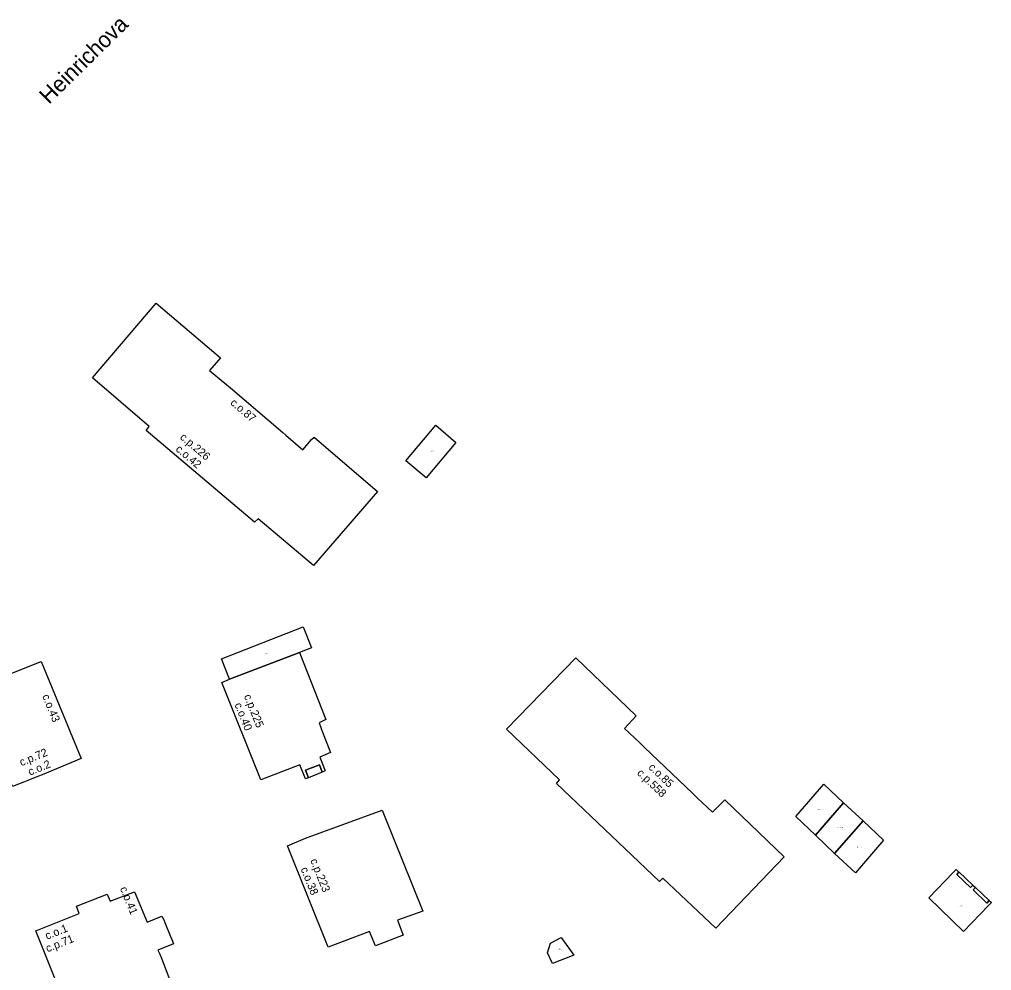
# Model space of a CAD drawing. Extents: x -600391 to -599491, y -1160176 to -1159402.
# Drawn here: x -599855.3 to -599733.8, y -1160060.9 to -1159942 of the extents above; entities that cross this region are included whole.
import ezdxf

# ---------------------------------------------------------------- set-up
doc = ezdxf.new("R2010")
doc.units = 0
for name, color, linetype in [('Level 10', 7, 'Continuous'), ('Level 11', 7, 'Continuous'), ('Level 12', 7, 'Continuous'), ('Level 24', 7, 'Continuous'), ('Level 25', 7, 'Continuous'), ('Level 61', 7, 'Continuous'), ('Level 62', 7, 'Continuous')]:
    doc.layers.add(name, color=color, linetype=linetype)

msp = doc.modelspace()

# ---------------------------------------------------------------- linework, layer by layer
at = {"layer": 'Level 61'}
for points in [[(-599846.11, -1159986.79), (-599838.15, -1159977.46)], [(-599838.15, -1159977.46), (-599830.14, -1159984.27)], [(-599830.38, -1159984.57), (-599831.49, -1159985.85)], [(-599830.14, -1159984.27), (-599830.38, -1159984.57)], [(-599831.49, -1159985.85), (-599829.34, -1159987.67)], [(-599839.05, -1159992.87), (-599846.11, -1159986.79)], [(-599829.34, -1159987.67), (-599828.89, -1159988.04)], [(-599828.89, -1159988.04), (-599822.35, -1159993.63)], [(-599839.43, -1159993.35), (-599839.05, -1159992.87)], [(-599825.9, -1160004.85), (-599839.43, -1159993.35)], [(-599806.96, -1159997.15), (-599803.22, -1159992.72)], [(-599803.22, -1159992.72), (-599800.7, -1159994.88)], [(-599822.35, -1159993.63), (-599821.98, -1159993.96)], [(-599821.98, -1159993.96), (-599819.85, -1159995.77)], [(-599819.85, -1159995.77), (-599818.74, -1159994.5)], [(-599818.74, -1159994.5), (-599818.44, -1159994.22)], [(-599818.44, -1159994.22), (-599810.51, -1160000.98)], [(-599800.7, -1159994.88), (-599804.44, -1159999.28)], [(-599804.44, -1159999.28), (-599806.96, -1159997.15)], [(-599810.51, -1160000.98), (-599818.49, -1160010.25)], [(-599825.44, -1160004.41), (-599825.9, -1160004.85)], [(-599818.49, -1160010.25), (-599825.44, -1160004.41)], [(-599830.02, -1160021.9), (-599819.78, -1160017.93)], [(-599819.78, -1160017.93), (-599818.76, -1160020.54)], [(-599820.24, -1160021.12), (-599829.01, -1160024.48)], [(-599829.01, -1160024.48), (-599820.24, -1160021.12)], [(-599818.76, -1160020.54), (-599820.24, -1160021.12)], [(-599820.24, -1160021.12), (-599816.96, -1160029.52)], [(-599862, -1160026.02), (-599852.53, -1160022.25)], [(-599852.53, -1160022.25), (-599847.55, -1160034.39)], [(-599829.01, -1160024.48), (-599830.02, -1160021.9)], [(-599794.37, -1160030.71), (-599785.73, -1160021.79)], [(-599785.73, -1160021.79), (-599778.18, -1160029.05)], [(-599829.97, -1160024.89), (-599829.01, -1160024.48)], [(-599825.1, -1160037.06), (-599829.97, -1160024.89)], [(-599816.96, -1160029.52), (-599817.81, -1160029.92)], [(-599778.18, -1160029.05), (-599779.64, -1160030.61)], [(-599817.81, -1160029.92), (-599817.37, -1160031.1)], [(-599817.37, -1160031.1), (-599816.37, -1160033.64)], [(-599787.75, -1160037.05), (-599794.37, -1160030.71)], [(-599779.64, -1160030.61), (-599777.77, -1160032.37)], [(-599777.77, -1160032.37), (-599777.16, -1160033)], [(-599777.16, -1160033), (-599771.15, -1160038.72)], [(-599847.55, -1160034.39), (-599852.41, -1160036.41)], [(-599816.37, -1160033.64), (-599817.71, -1160034.22)], [(-599817.71, -1160034.22), (-599817.04, -1160035.92)], [(-599820.22, -1160035.17), (-599825.1, -1160037.06)], [(-599819.49, -1160036.91), (-599820.22, -1160035.17)], [(-599817.76, -1160035.18), (-599819.49, -1160035.83)], [(-599819.49, -1160035.83), (-599817.76, -1160035.18)], [(-599819.49, -1160035.83), (-599819.14, -1160036.79)], [(-599819.14, -1160036.79), (-599819.49, -1160035.83)], [(-599817.42, -1160036.09), (-599817.76, -1160035.18)], [(-599817.76, -1160035.18), (-599817.42, -1160036.09)], [(-599817.04, -1160035.92), (-599817.42, -1160036.09)], [(-599854.22, -1160037.14), (-599854.64, -1160037.29)], [(-599852.87, -1160036.6), (-599854.22, -1160037.14)], [(-599852.41, -1160036.41), (-599852.87, -1160036.6)], [(-599819.14, -1160036.79), (-599819.49, -1160036.91)], [(-599817.42, -1160036.09), (-599819.14, -1160036.79)], [(-599788.13, -1160037.52), (-599787.75, -1160037.05)], [(-599854.64, -1160037.29), (-599856.12, -1160037.87)], [(-599775.25, -1160049.74), (-599788.13, -1160037.52)], [(-599758.25, -1160041.65), (-599754.75, -1160037.6)], [(-599754.75, -1160037.6), (-599752.27, -1160039.92)], [(-599771.15, -1160038.72), (-599770.52, -1160039.34)], [(-599770.52, -1160039.34), (-599768.64, -1160041.11)], [(-599768.64, -1160041.11), (-599767.09, -1160039.54)], [(-599767.09, -1160039.54), (-599759.67, -1160046.66)], [(-599819.5, -1160044.36), (-599809.93, -1160040.82)], [(-599809.93, -1160040.82), (-599804.86, -1160053.46)], [(-599755.76, -1160043.98), (-599752.27, -1160039.92)], [(-599752.27, -1160039.92), (-599755.76, -1160043.98)], [(-599752.27, -1160039.92), (-599749.81, -1160042.16)], [(-599755.76, -1160043.98), (-599758.25, -1160041.65)], [(-599753.4, -1160046.25), (-599749.81, -1160042.16)], [(-599749.81, -1160042.16), (-599753.4, -1160046.25)], [(-599749.81, -1160042.16), (-599747.29, -1160044.57)], [(-599821.75, -1160045.29), (-599819.5, -1160044.36)], [(-599753.4, -1160046.25), (-599755.76, -1160043.98)], [(-599816.68, -1160057.98), (-599821.75, -1160045.29)], [(-599747.29, -1160044.57), (-599750.76, -1160048.69)], [(-599759.67, -1160046.66), (-599768.24, -1160055.58)], [(-599750.76, -1160048.69), (-599753.4, -1160046.25)], [(-599741.62, -1160051.82), (-599738.55, -1160048.63)], [(-599738.55, -1160048.63), (-599738.19, -1160048.26)], [(-599738.19, -1160048.26), (-599738.14, -1160048.31)], [(-599738.14, -1160048.31), (-599737.89, -1160048.55)], [(-599737.84, -1160048.59), (-599738.12, -1160048.87)], [(-599738.12, -1160048.87), (-599737.84, -1160048.59)], [(-599738.12, -1160048.87), (-599736.39, -1160050.52)], [(-599736.39, -1160050.52), (-599738.12, -1160048.87)], [(-599737.89, -1160048.55), (-599737.84, -1160048.59)], [(-599737.84, -1160048.59), (-599737.82, -1160048.61)], [(-599737.82, -1160048.61), (-599736.09, -1160050.22)], [(-599774.87, -1160049.34), (-599775.25, -1160049.74)], [(-599768.24, -1160055.58), (-599774.87, -1160049.34)], [(-599736.39, -1160050.52), (-599736.1, -1160050.22)], [(-599736.09, -1160050.22), (-599736.39, -1160050.52)], [(-599736.1, -1160050.22), (-599736.09, -1160050.22)], [(-599736.09, -1160050.22), (-599735.78, -1160050.51)], [(-599735.78, -1160050.51), (-599736.08, -1160050.82)], [(-599736.08, -1160050.82), (-599735.78, -1160050.51)], [(-599735.78, -1160050.51), (-599734.05, -1160052.12)], [(-599848.14, -1160052.86), (-599844.29, -1160051.36)], [(-599844.29, -1160051.36), (-599843.93, -1160052.21)], [(-599843.93, -1160052.21), (-599840.86, -1160051.06)], [(-599840.86, -1160051.06), (-599839.31, -1160054.85)], [(-599736.08, -1160050.82), (-599734.38, -1160052.46)], [(-599734.38, -1160052.46), (-599736.08, -1160050.82)], [(-599847.79, -1160053.75), (-599848.14, -1160052.86)], [(-599737.27, -1160056.01), (-599741.62, -1160051.82)], [(-599734.16, -1160052.78), (-599737.27, -1160056.01)], [(-599734.38, -1160052.46), (-599734.05, -1160052.12)], [(-599734.05, -1160052.12), (-599734.38, -1160052.46)], [(-599733.77, -1160052.38), (-599734.16, -1160052.78)], [(-599734.05, -1160052.12), (-599733.81, -1160052.34)], [(-599733.81, -1160052.34), (-599733.77, -1160052.38)], [(-599853.2, -1160055.91), (-599847.79, -1160053.75)], [(-599839.31, -1160054.85), (-599837.46, -1160054.11)], [(-599837.46, -1160054.11), (-599837.23, -1160054.56)], [(-599804.86, -1160053.46), (-599808, -1160054.61)], [(-599837.23, -1160054.56), (-599837.07, -1160054.9)], [(-599837.07, -1160054.9), (-599836.38, -1160056.65)], [(-599808, -1160054.61), (-599807.3, -1160056.46)], [(-599848.48, -1160067.69), (-599853.2, -1160055.91)], [(-599811.52, -1160056), (-599816.68, -1160057.98)], [(-599810.76, -1160057.81), (-599811.52, -1160056)], [(-599807.3, -1160056.46), (-599810.76, -1160057.81)], [(-599836.01, -1160057.57), (-599837.94, -1160058.35)], [(-599836.38, -1160056.65), (-599836.21, -1160057.01)], [(-599836.21, -1160057.01), (-599836.01, -1160057.57)], [(-599789.26, -1160058.67), (-599788.87, -1160057.47)], [(-599788.87, -1160057.47), (-599787.56, -1160056.76)], [(-599787.56, -1160056.76), (-599785.97, -1160058.99)], [(-599837.94, -1160058.35), (-599837.73, -1160058.86)], [(-599837.73, -1160058.86), (-599837.6, -1160059.15)], [(-599788.65, -1160060.03), (-599789.26, -1160058.67)], [(-599785.97, -1160058.99), (-599788.65, -1160060.03)], [(-599837.6, -1160059.15), (-599836.6, -1160061.76)]]:
    msp.add_lwpolyline(points, dxfattribs=at)
at = {"layer": 'Level 62'}
for points in [[(-599830.14, -1159984.27), (-599830.38, -1159984.57), (-599831.49, -1159985.85), (-599829.34, -1159987.67), (-599828.89, -1159988.04), (-599822.35, -1159993.63), (-599821.98, -1159993.96), (-599819.85, -1159995.77), (-599818.74, -1159994.5), (-599818.44, -1159994.22), (-599810.51, -1160000.98), (-599818.49, -1160010.25), (-599825.44, -1160004.41), (-599825.9, -1160004.85), (-599839.43, -1159993.35), (-599839.05, -1159992.87), (-599846.11, -1159986.79), (-599838.15, -1159977.46), (-599830.14, -1159984.27)], [(-599806.96, -1159997.15), (-599803.22, -1159992.72), (-599800.7, -1159994.88), (-599804.44, -1159999.28), (-599806.96, -1159997.15)], [(-599820.24, -1160021.12), (-599829.01, -1160024.48), (-599830.02, -1160021.9), (-599819.78, -1160017.93), (-599818.76, -1160020.54), (-599820.24, -1160021.12)], [(-599820.24, -1160021.12), (-599816.96, -1160029.52), (-599817.81, -1160029.92), (-599817.37, -1160031.1), (-599816.37, -1160033.64), (-599817.71, -1160034.22), (-599817.04, -1160035.92), (-599817.42, -1160036.09), (-599817.76, -1160035.18), (-599819.49, -1160035.83), (-599819.14, -1160036.79), (-599819.49, -1160036.91), (-599820.22, -1160035.17), (-599825.1, -1160037.06), (-599829.97, -1160024.89), (-599829.01, -1160024.48), (-599820.24, -1160021.12)], [(-599852.41, -1160036.41), (-599852.87, -1160036.6), (-599854.22, -1160037.14), (-599854.64, -1160037.29), (-599856.12, -1160037.87), (-599857.6, -1160034.25), (-599858.54, -1160034.55), (-599860.61, -1160029.37), (-599860.77, -1160029.04), (-599861.26, -1160027.85), (-599861.42, -1160027.49), (-599862, -1160026.02), (-599852.53, -1160022.25), (-599847.55, -1160034.39), (-599852.41, -1160036.41)], [(-599770.52, -1160039.34), (-599768.64, -1160041.11), (-599767.09, -1160039.54), (-599759.67, -1160046.66), (-599768.24, -1160055.58), (-599774.87, -1160049.34), (-599775.25, -1160049.74), (-599788.13, -1160037.52), (-599787.75, -1160037.05), (-599794.37, -1160030.71), (-599785.73, -1160021.79), (-599778.18, -1160029.05), (-599779.64, -1160030.61), (-599777.77, -1160032.37), (-599777.16, -1160033), (-599771.15, -1160038.72), (-599770.52, -1160039.34)], [(-599817.42, -1160036.09), (-599819.14, -1160036.79), (-599819.49, -1160035.83), (-599817.76, -1160035.18), (-599817.42, -1160036.09)], [(-599752.27, -1160039.92), (-599755.76, -1160043.98), (-599758.25, -1160041.65), (-599754.75, -1160037.6), (-599752.27, -1160039.92)], [(-599807.3, -1160056.46), (-599810.76, -1160057.81), (-599811.52, -1160056), (-599816.68, -1160057.98), (-599821.75, -1160045.29), (-599819.5, -1160044.36), (-599809.93, -1160040.82), (-599804.86, -1160053.46), (-599808, -1160054.61), (-599807.3, -1160056.46)], [(-599753.4, -1160046.25), (-599755.76, -1160043.98), (-599752.27, -1160039.92), (-599749.81, -1160042.16), (-599753.4, -1160046.25)], [(-599753.4, -1160046.25), (-599749.81, -1160042.16), (-599747.29, -1160044.57), (-599750.76, -1160048.69), (-599753.4, -1160046.25)], [(-599737.89, -1160048.55), (-599737.84, -1160048.59), (-599738.12, -1160048.87), (-599736.39, -1160050.52), (-599736.1, -1160050.22), (-599736.09, -1160050.22), (-599735.78, -1160050.51), (-599736.08, -1160050.82), (-599734.38, -1160052.46), (-599734.05, -1160052.12), (-599733.81, -1160052.34), (-599733.77, -1160052.38), (-599734.16, -1160052.78), (-599737.27, -1160056.01), (-599741.62, -1160051.82), (-599738.55, -1160048.63), (-599738.19, -1160048.26), (-599738.14, -1160048.31), (-599737.89, -1160048.55)], [(-599737.82, -1160048.61), (-599736.09, -1160050.22), (-599736.39, -1160050.52), (-599738.12, -1160048.87), (-599737.84, -1160048.59), (-599737.82, -1160048.61)], [(-599735.78, -1160050.51), (-599734.05, -1160052.12), (-599734.38, -1160052.46), (-599736.08, -1160050.82), (-599735.78, -1160050.51)], [(-599837.07, -1160054.9), (-599836.38, -1160056.65), (-599836.21, -1160057.01), (-599836.01, -1160057.57), (-599837.94, -1160058.35), (-599837.73, -1160058.86), (-599837.6, -1160059.15), (-599836.6, -1160061.76), (-599836.43, -1160062.1), (-599836.19, -1160062.78), (-599848.48, -1160067.69), (-599853.2, -1160055.91), (-599847.79, -1160053.75), (-599848.14, -1160052.86), (-599844.29, -1160051.36), (-599843.93, -1160052.21), (-599840.86, -1160051.06), (-599839.31, -1160054.85), (-599837.46, -1160054.11), (-599837.23, -1160054.56), (-599837.07, -1160054.9)], [(-599787.56, -1160056.76), (-599785.97, -1160058.99), (-599788.65, -1160060.03), (-599789.26, -1160058.67), (-599788.87, -1160057.47), (-599787.56, -1160056.76)]]:
    msp.add_lwpolyline(points, dxfattribs=at)

# ---------------------------------------------------------------- texts
at = {"layer": 'Level 10'}
for s, rotation, p in [('c.o.87', 319.5423, (-599828.99, -1159990.03)), ('c.o.42', 319.6398, (-599835.82, -1159995.83)), ('c.o.43', 292.3025, (-599852.44, -1160026.57)), ('c.o.40', 291.8269, (-599828.4, -1160027.63)), ('c.o.2', 22.2461, (-599853.94, -1160036.54)), ('c.o.85', 316.252, (-599776.72, -1160035.57)), ('c.o.38', 291.778, (-599820.13, -1160048.18)), ('c.o.41', 292.2408, (-599842.72, -1160050.63)), ('c.o.1', 21.7652, (-599851.81, -1160057.05))]:
    msp.add_text(s, height=1, rotation=rotation, dxfattribs=at).set_placement(p)
at = {"layer": 'Level 11'}
msp.add_text('Heinrichova', height=2, rotation=44.5818, dxfattribs=at).set_placement((-599851.57, -1159952.66))
at = {"layer": 'Level 12'}
for s, rotation, p in [('c.p.226', 319.6398, (-599835.28, -1159994.34)), ('c.p.225', 291.8269, (-599827.22, -1160026.57)), ('c.p.72', 22.2461, (-599855.01, -1160035.36)), ('c.p.558', 316.252, (-599778.15, -1160036.29)), ('c.p.223', 291.778, (-599818.93, -1160047.12)), ('c.p.71', 21.7652, (-599851.74, -1160058.63))]:
    msp.add_text(s, height=1, rotation=rotation, dxfattribs=at).set_placement(p)
at = {"layer": 'Level 24'}
for s, p in [('c.z.356', (-599824.58, -1160021.21)), ('c.z.1662', (-599737.95, -1160052.88))]:
    msp.add_text(s, height=0.1, dxfattribs=at).set_placement(p)
at = {"layer": 'Level 25'}
for s, p in [('c.pp.226_A', (-599804.12, -1159996.01)), ('c.pp.558_A', (-599755.56, -1160040.8)), ('c.pp.558_B', (-599753.07, -1160043.05)), ('c.pp.558_C', (-599750.69, -1160045.49)), ('c.pp.223_B', (-599788.12, -1160058.22))]:
    msp.add_text(s, height=0.1, dxfattribs=at).set_placement(p)

doc.saveas('drawing.dxf')
